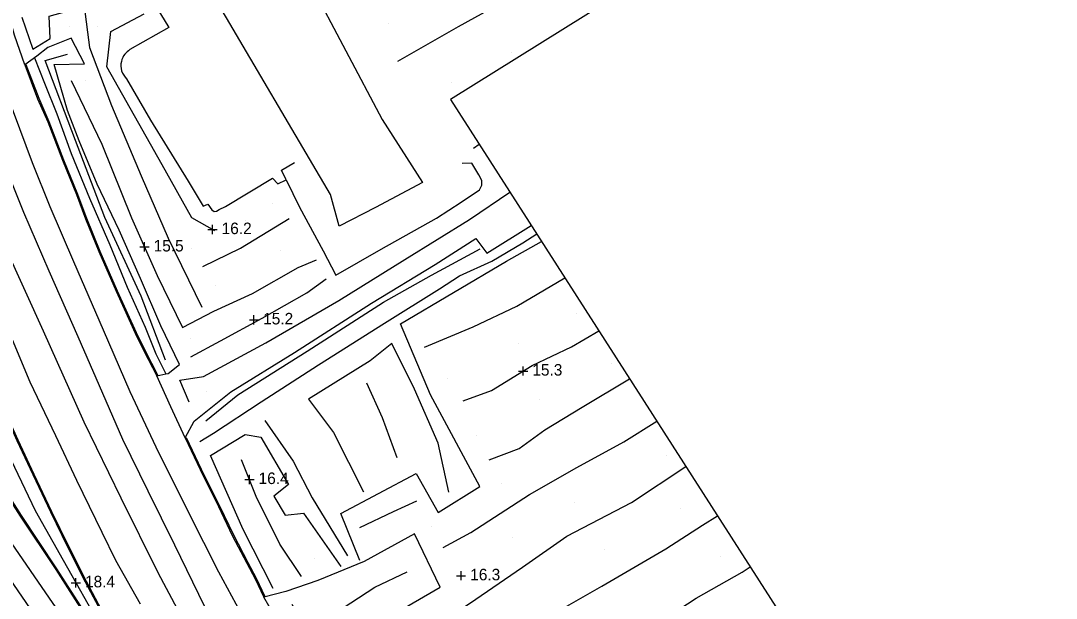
# Model space of a CAD drawing. Extents: x 2316231 to 2323598, y 363169 to 371906.
# Drawn here: x 2318067.7 to 2318516.9, y 368495.1 to 368745.7 of the extents above; entities that cross this region are included whole.
import ezdxf

# ---------------------------------------------------------------- set-up
doc = ezdxf.new("R2010")
doc.units = 0
for name, color, linetype in [('RD_DTM_BkLn1', 7, 'Continuous'), ('RD_DTM_Spot', 7, 'Continuous'), ('RD_DTM_TinHull', 7, 'Continuous'), ('RD_DTM_Void', 7, 'Continuous'), ('RD_EX_Road', 7, 'Continuous')]:
    doc.layers.add(name, color=color, linetype=linetype)

msp = doc.modelspace()

# ---------------------------------------------------------------- linework, layer by layer
at = {"layer": 'RD_DTM_BkLn1'}
msp.add_line((2318264.186, 368690.444), (2318266.559, 368692.124), dxfattribs=at)
for points in [[(2317994.945, 368943.256), (2317999.581, 368922.486), (2318006.415, 368894.237), (2318012.687, 368867.615), (2318018.739, 368844.567), (2318025.715, 368820.723), (2318032.954, 368796.181), (2318042.568, 368767.866), (2318051.932, 368740.972), (2318061.741, 368713.692), (2318072.652, 368684.171), (2318080.313, 368665.019), (2318090.671, 368641.168), (2318103.423, 368611.607), (2318115.122, 368584.84), (2318126.37, 368560.77), (2318140.521, 368532.325), (2318153.45, 368506.603), (2318162.871, 368489.204)], [(2318231.245, 368728.124), (2318257.55, 368743.11), (2318285.998, 368758.946), (2318316.356, 368778.038), (2318352.81, 368800.5), (2318385.467, 368820.261), (2318423.718, 368844.319), (2318452.479, 368859.998), (2318470.209, 368872.547), (2318496.711, 368889.663), (2318530.355, 368909.507), (2318549.888, 368920.861), (2318577.558, 368938.118)], [(2317800.727, 368903.713), (2317822.559, 368871.316), (2317848.195, 368833.555), (2317873.003, 368797.108), (2317897.118, 368762.937), (2317918.852, 368734.909), (2317938.14, 368706.056), (2317957.247, 368676.396), (2317975.021, 368648.353), (2317993.334, 368624.472), (2318012.682, 368595.462), (2318033.529, 368563.765), (2318053.633, 368533.466), (2318080.086, 368495.162), (2318097.769, 368469.694), (2318114.655, 368442.844), (2318134.076, 368413.87), (2318156.078, 368381.786), (2318175.29, 368356.772), (2318189.565, 368335.319)], [(2318128.541, 368755.619), (2318149.504, 368765.935), (2318167.781, 368775.367), (2318181.682, 368781.137), (2318192.93, 368762.507), (2318224.475, 368702.806), (2318242.058, 368675.521), (2318221.599, 368664.71), (2318205.84, 368656.549), (2318202.139, 368670.313), (2318152.285, 368755.23), (2318177.664, 368770.748)], [(2318068.157, 368747.219), (2318072.976, 368733.332), (2318080.46, 368737.889), (2318080.096, 368747.65), (2318095.293, 368751.829), (2318097.637, 368734.012), (2318107.162, 368708.875), (2318120.02, 368678.447), (2318131.743, 368651.416), (2318146.228, 368621.43)], [(2318151.86, 368654.549), (2318141.896, 368660.143), (2318129.081, 368683.157), (2318105.044, 368725.668), (2318106.763, 368740.997), (2318121.269, 368748.667)], [(2317941.601, 368736.7), (2317960.274, 368728.753), (2317984.699, 368726.449), (2318000.484, 368696.797), (2318016.398, 368660.117), (2318030.777, 368625.931), (2318048.928, 368588.644), (2318060.554, 368561.456), (2318074.007, 368533.157), (2318086.079, 368511.649), (2318102.491, 368482.766)], [(2318130.532, 368598.478), (2318119.906, 368626.133), (2318104.167, 368660.298), (2318091.556, 368693.758), (2318078.309, 368728.422), (2318087.991, 368731.193)], [(2318089.663, 368719.721), (2318102.925, 368692.18), (2318115.744, 368660.176), (2318126.942, 368635.204), (2318137.911, 368612.663), (2318151.531, 368619.637), (2318168.216, 368627.363), (2318188.146, 368638.572), (2318196.012, 368642.021)], [(2318049.725, 368711.287), (2318058.58, 368688.161), (2318068.971, 368662.601), (2318079.879, 368637.124), (2318092.513, 368608.658), (2318101.817, 368587.421), (2318111.924, 368564.087), (2318122.839, 368541.811), (2318134.425, 368518.318), (2318144.884, 368496.886)], [(2318140.806, 368580.235), (2318136.747, 368589.823), (2318147.04, 368591.378), (2318174.09, 368605.977), (2318205.649, 368624.261), (2318234.355, 368642.081), (2318262.325, 368659.495), (2318279.893, 368671.327)], [(2318146.772, 368638.999), (2318163, 368647.075), (2318184.233, 368659.906)], [(2318145.462, 368563.136), (2318151.355, 368566.745), (2318172.049, 368580.407), (2318196.959, 368596.467), (2318225.533, 368614.541), (2318249.37, 368629.376), (2318258.023, 368634.977), (2318272.058, 368641.313), (2318285.494, 368649.347), (2318291.531, 368653.176)], [(2318061.187, 368647.202), (2318077.511, 368611.086), (2318095.044, 368571.67), (2318111.086, 368538.72), (2318127.178, 368506.372), (2318144.03, 368474.816), (2318164.713, 368439.858), (2318181.683, 368407.388), (2318202.506, 368370.167)], [(2318147.985, 368572.12), (2318161.934, 368583.366), (2318191.954, 368602.267), (2318225.156, 368623.52), (2318245.941, 368635.329), (2318267.087, 368646.691)], [(2318141.583, 368599.898), (2318154.451, 368606.778), (2318172.453, 368616.667), (2318191.793, 368627.673), (2318200.158, 368633.66)], [(2318242.9, 368604.057), (2318264.004, 368612.82), (2318282.906, 368621.793), (2318303.724, 368634.16)], [(2318061.785, 368612.637), (2318071.734, 368589.003), (2318082.84, 368565.764), (2318091.919, 368546.308), (2318102.966, 368523.803), (2318108.909, 368511.719), (2318119.482, 368492.765)], [(2318259.65, 368580.757), (2318271.971, 368585.219), (2318289.506, 368596.121), (2318306.576, 368604.207), (2318318.505, 368611.107)], [(2318253.45, 368541.153), (2318248.839, 368562.488), (2318238.528, 368585.918), (2318228.715, 368605.592), (2318219.263, 368598.115), (2318192.582, 368581.518), (2318203.43, 368567.04), (2318216.359, 368541.33)], [(2318231.062, 368556.065), (2318224.697, 368573.408), (2318217.834, 368588.491)], [(2318270.967, 368555.147), (2318283.939, 368560.173), (2318295.089, 368568.26), (2318311.321, 368577.973), (2318331.821, 368590.338)], [(2318173.559, 368572.184), (2318185.965, 368554.647), (2318194.101, 368538.767), (2318209.499, 368513.605)], [(2318251.026, 368517.125), (2318262.991, 368523.645), (2318288.42, 368540.113), (2318309.001, 368551.935), (2318329.292, 368562.95), (2318343.616, 368571.942)], [(2318189.466, 368504.587), (2318180.181, 368518.567), (2318169.853, 368539.35), (2318163.533, 368555.177)], [(2318241.243, 368479.032), (2318262.406, 368492.85), (2318285.367, 368508.686), (2318304.64, 368522.026), (2318332.64, 368536.695), (2318356.237, 368552.259)], [(2318214.797, 368525.797), (2318229.458, 368532.853), (2318239.554, 368537.464)], [(2318256.621, 368461.284), (2318274.492, 368472.064), (2318297.56, 368487.61), (2318319.864, 368500.378), (2318347.555, 368516.529), (2318363.452, 368526.904), (2318369.907, 368530.939)], [(2318185.287, 368492.561), (2318187.925, 368487.994), (2318195.792, 368475.232), (2318203.788, 368488.501), (2318221.359, 368499.992), (2318235.286, 368506.653)], [(2318266.409, 368441.273), (2318287.531, 368452.443), (2318314.53, 368465.923), (2318335.667, 368478.826), (2318360.771, 368495.15), (2318380.593, 368506.504), (2318384.133, 368508.752)], [(2318144.884, 368496.886), (2318156.518, 368473.032), (2318176.299, 368438.22), (2318198.994, 368398.492), (2318216.607, 368368.391), (2318230.329, 368347.481)]]:
    msp.add_lwpolyline(points, dxfattribs=at)
at = {"layer": 'RD_DTM_Spot'}
for p, q in [((2318227.153, 368744.308), (2318227.153, 368744.308)), ((2318089.04, 368743.105), (2318089.04, 368743.105)), ((2318100.894, 368742.995), (2318100.894, 368742.995)), ((2318304.642, 368743.163), (2318304.642, 368743.163)), ((2318280.608, 368731.891), (2318280.608, 368731.891)), ((2318095.764, 368719.719), (2318095.764, 368719.719)), ((2318254.584, 368718.722), (2318254.584, 368718.722)), ((2318177.111, 368666.456), (2318177.111, 368666.456)), ((2318165.168, 368659.117), (2318165.168, 368659.117)), ((2318141.794, 368646.917), (2318141.794, 368646.917)), ((2318180.303, 368646.002), (2318180.303, 368646.002)), ((2318152.326, 368630.828), (2318152.326, 368630.828)), ((2318308.678, 368618.571), (2318308.678, 368618.571)), ((2318141.588, 368607.757), (2318141.588, 368607.757)), ((2318283.437, 368605.858), (2318283.437, 368605.858)), ((2318323.963, 368596.888), (2318323.963, 368596.888)), ((2318252.932, 368590.52), (2318252.932, 368590.52)), ((2318148.122, 368584.997), (2318148.122, 368584.997)), ((2318292.554, 368581.528), (2318292.554, 368581.528)), ((2318265.309, 368565.666), (2318265.309, 368565.666)), ((2318347.74, 368557.169), (2318347.74, 368557.169)), ((2318276.179, 368544.774), (2318276.179, 368544.774)), ((2318307.945, 368536.641), (2318307.945, 368536.641)), ((2318353.888, 368534.254), (2318353.888, 368534.254)), ((2318245.823, 368526.343), (2318245.823, 368526.343)), ((2318281.11, 368521.403), (2318281.11, 368521.403)), ((2318320.825, 368516.142), (2318320.825, 368516.142)), ((2318194.994, 368512.337), (2318194.994, 368512.337)), ((2318371.281, 368513.336), (2318371.281, 368513.336)), ((2318258.714, 368504.929), (2318258.714, 368504.929))]:
    msp.add_line(p, q, dxfattribs=at)
at = {"layer": 'RD_DTM_TinHull'}
msp.add_lwpolyline([(2319557.442, 369523.873), (2318254.179, 368711.432), (2318782.433, 367887.547), (2318500.627, 367718.473), (2317350.395, 369314.708)], dxfattribs=at)
at = {"layer": 'RD_DTM_Void'}
for p, q in [((2318148.885, 368655.096), (2318152.885, 368655.096)), ((2318150.885, 368653.096), (2318150.885, 368657.096)), ((2318121.399, 368645.566), (2318121.399, 368649.566)), ((2318119.399, 368647.566), (2318123.399, 368647.566)), ((2318168.901, 368613.941), (2318168.901, 368617.941)), ((2318166.901, 368615.941), (2318170.901, 368615.941)), ((2318285.652, 368591.725), (2318285.652, 368595.725)), ((2318283.652, 368593.725), (2318287.652, 368593.725)), ((2318164.923, 368546.687), (2318168.923, 368546.687)), ((2318166.923, 368544.687), (2318166.923, 368548.687)), ((2318258.714, 368502.929), (2318258.714, 368506.929)), ((2318089.63, 368501.88), (2318093.63, 368501.88)), ((2318091.63, 368499.88), (2318091.63, 368503.88)), ((2318256.714, 368504.929), (2318260.714, 368504.929))]:
    msp.add_line(p, q, dxfattribs=at)
at = {"layer": 'RD_EX_Road'}
for p in [(2318126.75, 368591.59), (2318130.659, 368592.48)]:
    msp.add_line(p, (2318130.659, 368592.48), dxfattribs=at)
for points in [[(2318196.224, 368771.802), (2318184.576, 368794.513), (2318164.454, 368783.521), (2318140.774, 368769.288), (2318124.844, 368760.056), (2318124.06, 368758.987), (2318123.876, 368757.687), (2318124.748, 368754.532), (2318131.943, 368742.663), (2318115.013, 368733.168)], [(2318069.447, 368726.504), (2318065.107, 368739.439), (2318061.728, 368751.469)], [(2318130.659, 368592.48), (2318131.675, 368592.711), (2318136.666, 368596.611), (2318128.519, 368613.345), (2318119.706, 368633.884), (2318110.365, 368654.748), (2318100.853, 368674.771), (2318093.072, 368693.622), (2318088.07, 368706.751), (2318082.265, 368726.621), (2318095.335, 368726.929), (2318089.547, 368738.146), (2318079.549, 368734.04), (2318074.703, 368730.356), (2318069.447, 368726.504)], [(2317998.755, 368731.641), (2318003.419, 368718.152), (2318012.136, 368692.331), (2318019.447, 368673.047), (2318026.101, 368656.316), (2318032.711, 368641.006), (2318038.852, 368625.793), (2318045.976, 368609.362), (2318053.257, 368592.774), (2318058.396, 368581.571), (2318066.552, 368563.838), (2318073.404, 368548.972), (2318081.107, 368532.804), (2318088.439, 368517.745), (2318096.132, 368502.504), (2318105.193, 368485.383)], [(2318069.447, 368726.504), (2318075.072, 368711.846), (2318079.49, 368701.799), (2318085.784, 368685.153), (2318091.865, 368670.301), (2318095.838, 368659.774), (2318101.583, 368645.501), (2318109.08, 368628.335), (2318117.404, 368610.192), (2318121.07, 368602.518), (2318126.75, 368591.59)], [(2318069.914, 368726.683), (2318075.534, 368712.036), (2318079.953, 368701.988), (2318086.25, 368685.337), (2318092.331, 368670.484), (2318096.304, 368659.956), (2318102.045, 368645.694), (2318109.536, 368628.539), (2318117.857, 368610.404), (2318121.517, 368602.741), (2318127.194, 368591.821)], [(2318073.724, 368729.638), (2318078.047, 368718.639), (2318083.421, 368705.232), (2318089.678, 368688.021), (2318097.566, 368668.652), (2318106.392, 368648.487), (2318113.897, 368630.142), (2318121.742, 368612.758), (2318126.29, 368601.147), (2318130.659, 368592.48)], [(2318113.613, 368720.414), (2318124.081, 368702.532), (2318140.318, 368676.032), (2318146.865, 368665.187), (2318148.937, 368666.145), (2318150.688, 368663.614), (2318151.662, 368662.866), (2318152.589, 368663.104), (2318153.866, 368663.787), (2318156.517, 368665.154), (2318176.93, 368677.36), (2318179.235, 368674.864), (2318182.838, 368676.661)], [(2318182.838, 368676.661), (2318180.909, 368680.914), (2318186.488, 368684.151)], [(2318182.838, 368676.661), (2318188.648, 368664.734), (2318198.849, 368645.866), (2318204.422, 368635.323), (2318224.147, 368646.52), (2318248.053, 368659.959), (2318258.791, 368666.916), (2318266.686, 368672.326), (2318267.737, 368674.333), (2318267.706, 368676.392), (2318266.508, 368678.849), (2318263.438, 368683.91), (2318259.165, 368683.775)], [(2318021.088, 368667.569), (2318025.639, 368656.125), (2318032.25, 368640.813), (2318038.39, 368625.6), (2318045.518, 368609.162), (2318052.801, 368592.569), (2318057.941, 368581.362), (2318066.098, 368563.628), (2318072.951, 368548.76), (2318080.656, 368532.587), (2318087.991, 368517.523), (2318095.688, 368502.275), (2318104.739, 368485.171)], [(2318139.087, 368564.666), (2318142.906, 368571.999), (2318158.868, 368584.733), (2318186.441, 368601.713), (2318219.908, 368623.146), (2318247.48, 368639.995), (2318265.123, 368651.136), (2318269.947, 368644.892), (2318289.197, 368656.816)], [(2318214.826, 368511.596), (2318206.566, 368531.868), (2318239.254, 368549.271), (2318248.785, 368532.39), (2318266.85, 368543.651), (2318245.467, 368583.352), (2318232.428, 368614.153), (2318278.472, 368641.371), (2318293.596, 368649.955)], [(2318098.533, 368483.268), (2318083.037, 368507.588), (2318067.623, 368530.812), (2318053.566, 368552.565), (2318037.807, 368577.584), (2318019.038, 368607.17)], [(2318098.944, 368483.553), (2318083.456, 368507.86), (2318068.042, 368531.086), (2318053.988, 368552.834), (2318038.23, 368577.851), (2318019.458, 368607.441)], [(2318139.087, 368564.666), (2318132.799, 368578.134), (2318126.75, 368591.59)], [(2318139.087, 368564.666), (2318145.568, 368550.98), (2318153.512, 368535.017), (2318159.514, 368522.44), (2318165.818, 368510.439), (2318169.401, 368503.572), (2318173.223, 368495.644)], [(2318139.539, 368564.88), (2318146.018, 368551.199), (2318153.962, 368535.236), (2318159.961, 368522.664), (2318166.261, 368510.671), (2318169.848, 368503.796), (2318173.674, 368495.862)], [(2318177.191, 368499.354), (2318164.261, 368525.041), (2318150.022, 368557.108), (2318165.146, 368566.234), (2318171.871, 368565.015), (2318183.86, 368544.506), (2318177.555, 368539.441), (2318182.471, 368531.139), (2318190.416, 368532), (2318206.528, 368508.954)], [(2318199.017, 368460.997), (2318201.397, 368468.577), (2318214.285, 368478.754), (2318228.939, 368488.001), (2318249.617, 368499.954), (2318238.572, 368523.145), (2318216.69, 368511.086), (2318196.538, 368502.826), (2318182.772, 368498.151), (2318173.223, 368495.644)], [(2318061.203, 368506.143), (2318075.287, 368485.545), (2318089.083, 368465.754), (2318102.038, 368446.133), (2318105.205, 368441.613), (2318108.218, 368443.375), (2318123.248, 368420.766), (2318140.401, 368395.082), (2318159.883, 368366.602), (2318173.451, 368346.799), (2318187.621, 368327.115), (2318203.747, 368304.551), (2318220.506, 368280.385), (2318238.247, 368253.557), (2318254.385, 368231.245), (2318256.323, 368228.817)], [(2318197.023, 368454.723), (2318188.426, 368469.652), (2318179.697, 368484.39), (2318173.223, 368495.644)]]:
    msp.add_lwpolyline(points, dxfattribs=at)
msp.add_spline([(2318115.013, 368733.168), (2318112.867, 368731.103), (2318111.38, 368728.037), (2318111.515, 368723.885), (2318113.613, 368720.414)], degree=3, dxfattribs=at)

# ---------------------------------------------------------------- texts
at = {"layer": 'RD_DTM_Void'}
for s, p in [('16.2', (2318154.885, 368653.096)), ('15.5', (2318125.399, 368645.566)), ('15.2', (2318172.901, 368613.941)), ('15.3', (2318289.652, 368591.725)), ('16.4', (2318170.923, 368544.687)), ('16.3', (2318262.714, 368502.929)), ('18.4', (2318095.63, 368499.88))]:
    msp.add_text(s, height=5, dxfattribs=at).set_placement(p)

doc.saveas('drawing.dxf')
